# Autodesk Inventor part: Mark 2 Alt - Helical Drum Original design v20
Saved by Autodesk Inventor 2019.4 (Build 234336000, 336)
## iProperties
Created: 2020-06
Part Number: Mark 2 Alt - Helical Drum Original design v20
Material: Generic
Document SubType Name: Modeling
Designer: Administrator
Density: 1 g/cm^3
Appearance: Default
Author: Administrator
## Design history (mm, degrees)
feature "Body1"
body "Solid1"
